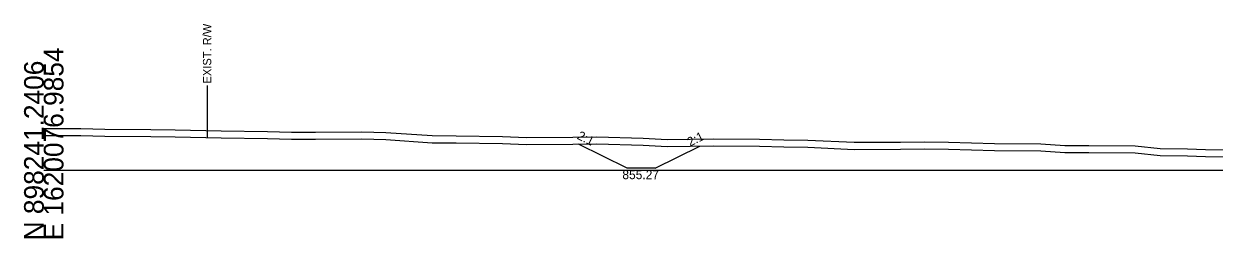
# Model space of a CAD drawing. Extents: x -26 to 2403, y -11 to 9582.
# Drawn here: x 997.2 to 1166.5, y 4990.3 to 5020.9 of the extents above; entities that cross this region are included whole.
import ezdxf

# ---------------------------------------------------------------- set-up
doc = ezdxf.new("R2010")
doc.units = 0
for name, color, linetype in [('Exist Cross Section Cell', 7, 'Continuous'), ('Exist XS Ground Line', 7, 'Continuous'), ('Old_Level_10', 7, 'Continuous'), ('Prop CMT Slope Grass', 7, 'Continuous'), ('Prop XS DDE Slope Text', 7, 'Continuous'), ('Prop XS Hydro Elevations', 7, 'Continuous'), ('Scratch_Level_6', 7, 'Continuous')]:
    doc.layers.add(name, color=color, linetype=linetype)

msp = doc.modelspace()

# ---------------------------------------------------------------- linework, layer by layer
at = {"layer": 'Exist Cross Section Cell'}
msp.add_line((1000, 5000), (1200, 5000), dxfattribs=at)
at = {"layer": 'Exist XS Ground Line'}
msp.add_lwpolyline([(1000, 5004.92), (1005.25, 5004.92), (1008.67, 5004.84), (1015.25, 5004.79), (1018.67, 5004.76), (1025.25, 5004.6), (1031.83, 5004.5), (1035.25, 5004.44), (1038.67, 5004.4), (1045.25, 5004.48), (1048.67, 5004.38), (1055.25, 5003.92), (1058.67, 5003.89), (1065.25, 5003.78), (1068.67, 5003.65), (1075.25, 5003.7), (1078.67, 5003.74), (1085.25, 5003.55), (1088.67, 5003.39), (1095.25, 5003.46), (1101.83, 5003.4), (1105.25, 5003.34), (1108.67, 5003.29), (1115.25, 5002.97), (1121.84, 5003.01), (1125.25, 5003.03), (1128.67, 5003.01), (1135.25, 5002.79), (1141.84, 5002.76), (1145.25, 5002.53), (1148.67, 5002.51), (1155.26, 5002.46), (1158.79, 5002.08), (1162.68, 5002.04), (1165.26, 5001.96), (1169.84, 5001.91)], dxfattribs=at)
msp.add_lwpolyline([(1000, 5004.92), (1005.25, 5004.92), (1008.67, 5004.84), (1015.25, 5004.79), (1018.67, 5004.76), (1025.25, 5004.6), (1031.83, 5004.5), (1035.25, 5004.44), (1038.67, 5004.4), (1045.25, 5004.48), (1048.67, 5004.38), (1055.25, 5003.92), (1058.67, 5003.89), (1065.25, 5003.78), (1068.67, 5003.65), (1075.25, 5003.7), (1078.67, 5003.74), (1085.25, 5003.55), (1088.67, 5003.39), (1095.25, 5003.46), (1101.83, 5003.4), (1105.25, 5003.34), (1108.67, 5003.29), (1115.25, 5002.97), (1121.84, 5003.01), (1125.25, 5003.03), (1128.67, 5003.01), (1135.25, 5002.79), (1141.84, 5002.76), (1145.25, 5002.53), (1148.67, 5002.51), (1155.26, 5002.46), (1158.79, 5002.08), (1162.68, 5002.04), (1165.26, 5001.96), (1169.84, 5001.91)], dxfattribs=at)
at = {"layer": 'Old_Level_10'}
msp.add_line((1023.23, 5012.05), (1023.23, 5004.65), dxfattribs=at)
at = {"layer": 'Prop CMT Slope Grass'}
for p, q in [((1082.96, 5000.27), (1076.08, 5003.71)), ((1086.96, 5000.27), (1093.31, 5003.44)), ((1086.96, 5000.27), (1082.96, 5000.27))]:
    msp.add_line(p, q, dxfattribs=at)
at = {"layer": 'Scratch_Level_6'}
msp.add_lwpolyline([(1000, 5005.92), (1005.25, 5005.92), (1008.67, 5005.84), (1015.25, 5005.79), (1018.67, 5005.76), (1025.25, 5005.6), (1031.83, 5005.5), (1035.25, 5005.44), (1038.67, 5005.4), (1045.25, 5005.48), (1048.67, 5005.38), (1055.25, 5004.92), (1058.67, 5004.89), (1065.25, 5004.78), (1068.67, 5004.65), (1075.25, 5004.7), (1078.67, 5004.74), (1085.25, 5004.55), (1088.67, 5004.39), (1095.25, 5004.46), (1101.83, 5004.4), (1105.25, 5004.34), (1108.67, 5004.29), (1115.25, 5003.97), (1121.84, 5004.01), (1125.25, 5004.03), (1128.67, 5004.01), (1135.25, 5003.79), (1141.84, 5003.76), (1145.25, 5003.53), (1148.67, 5003.51), (1155.26, 5003.46), (1158.79, 5003.08), (1162.68, 5003.04), (1165.26, 5002.96), (1169.84, 5002.91)], dxfattribs=at)

# ---------------------------------------------------------------- texts
at = {"layer": 'Exist Cross Section Cell'}
for s, p in [('E 1620076.9854', (1002.8, 4990)), ('N 898241.2406', (1000, 4990))]:
    msp.add_text(s, height=2.8, rotation=90, dxfattribs=at).set_placement(p)
at = {"layer": 'Old_Level_10'}
msp.add_text('EXIST. R/W', height=1.181, rotation=90, dxfattribs=at).set_placement((1023.82, 5012.35))
at = {"layer": 'Prop XS DDE Slope Text'}
for rotation, p in [(333.4349, (1075.76, 5004.51)), (26.5651, (1091.92, 5003.35))]:
    msp.add_text('2:1', height=1.275, rotation=rotation, dxfattribs=at).set_placement(p)
at = {"layer": 'Prop XS Hydro Elevations'}
msp.add_text('855.27', height=1.275, dxfattribs=at).set_placement((1082.3, 4998.72))

doc.saveas('drawing.dxf')
